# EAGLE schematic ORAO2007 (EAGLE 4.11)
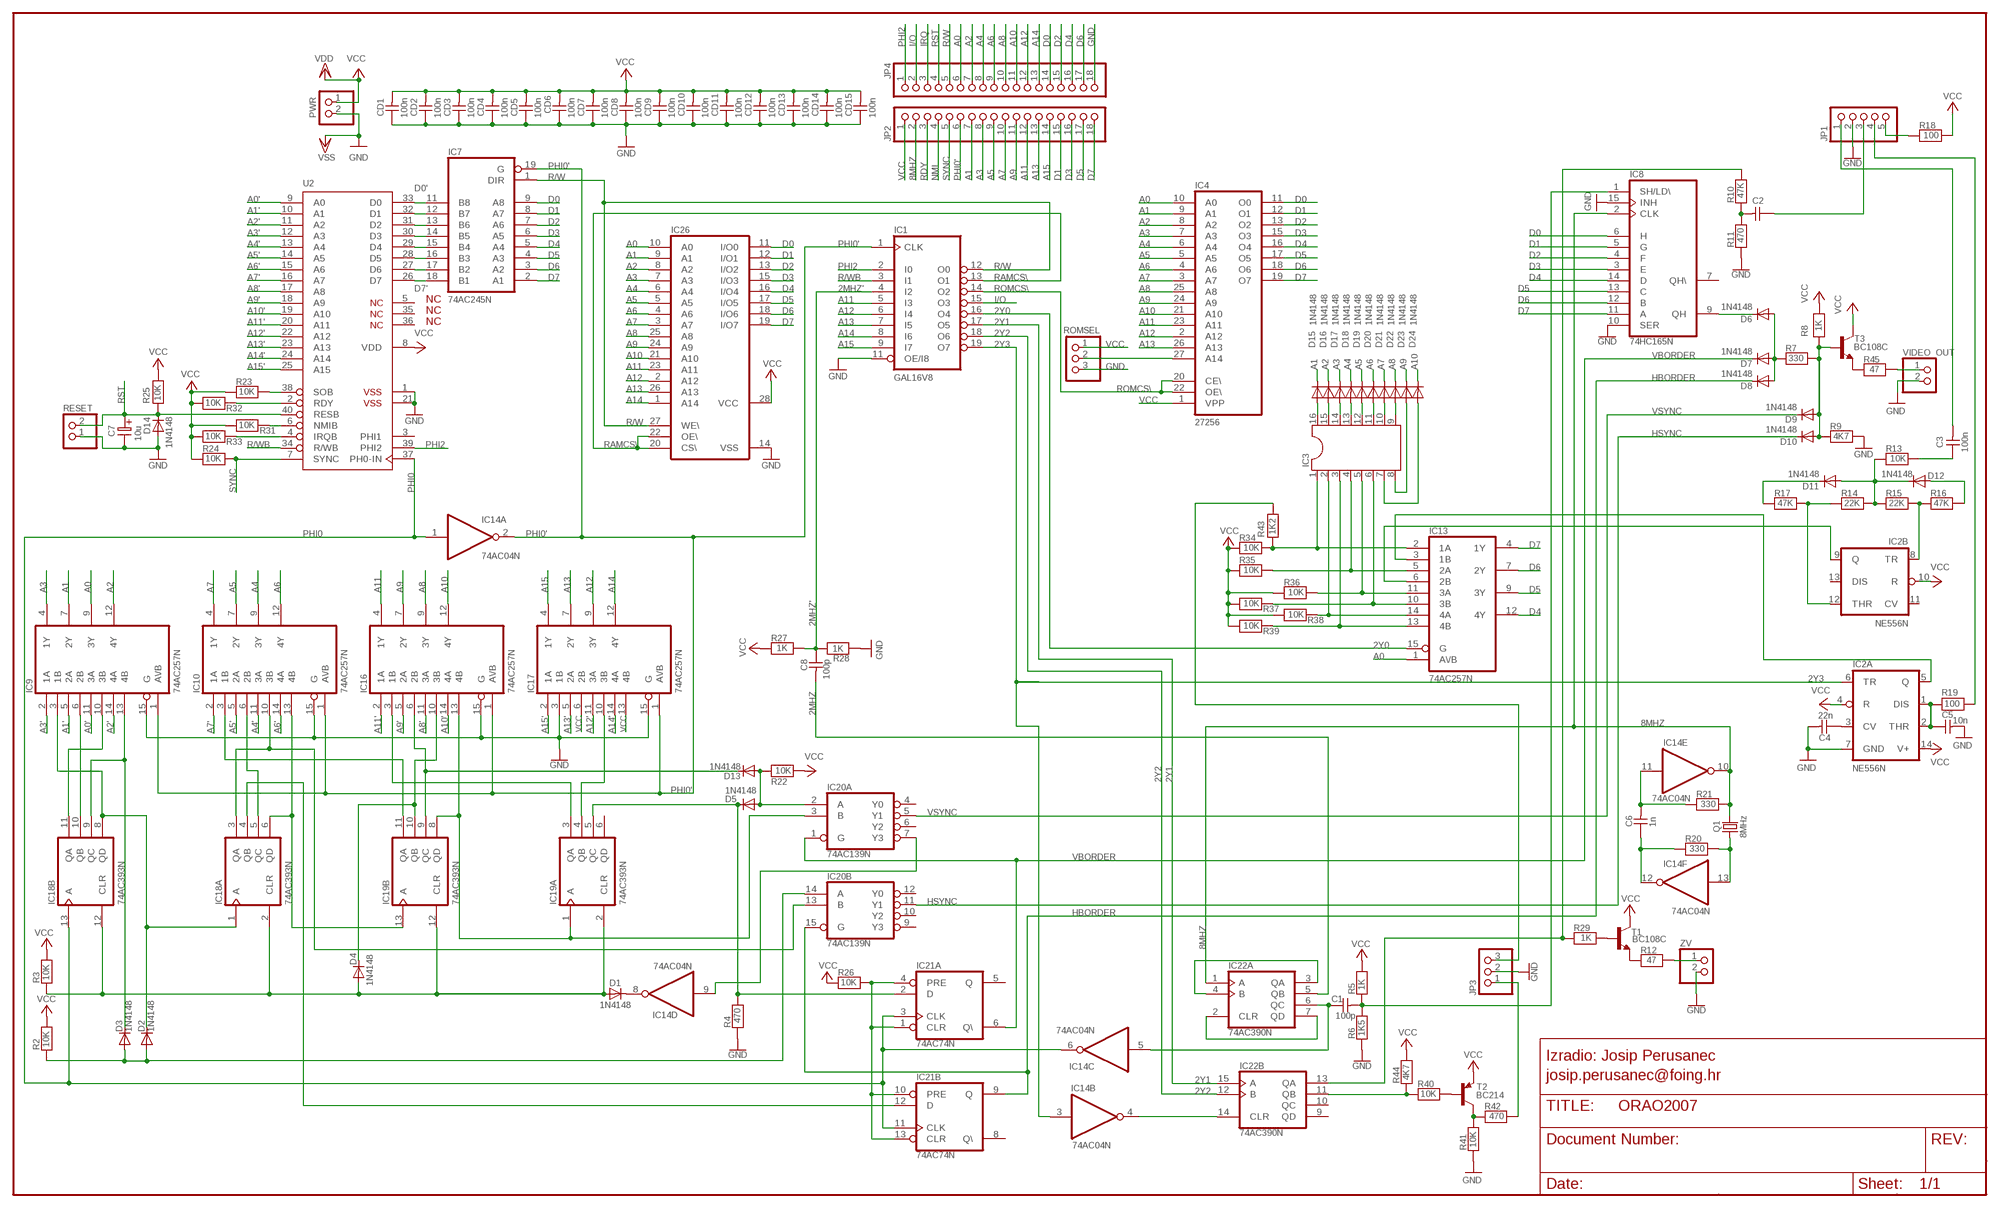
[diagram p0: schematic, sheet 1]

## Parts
C1  100p  CAPNP-5  [C-5]
C2  CAPNP-5  [C-5]
C3  100n  CAPNP-5  [C-5]
C4  22n  CAPNP-5  [C-5]
C5  10n  CAPNP-5  [C-5]
C6  1n  CAPNP-5  [C-5]
C7  10u  ELC-2,5L  [ES-2,5L]
C8  100p  CAPNP-5  [C-5]
CD1  100n  CAPNP-5  [C-5]
CD2  100n  CAPNP-5  [C-5]
CD3  100n  CAPNP-5  [C-5]
CD4  100n  CAPNP-5  [C-5]
CD5  100n  CAPNP-5  [C-5]
CD6  100n  CAPNP-5  [C-5]
CD7  100n  CAPNP-5  [C-5]
CD8  100n  CAPNP-5  [C-5]
CD9  100n  CAPNP-5  [C-5]
CD10  100n  CAPNP-5  [C-5]
CD11  100n  CAPNP-5  [C-5]
CD12  100n  CAPNP-5  [C-5]
CD13  100n  CAPNP-5  [C-5]
CD14  100n  CAPNP-5  [C-5]
CD15  100n  CAPNP-5  [C-5]
D1  1N4148  [DO35-10]
D2  1N4148  [DO35-10]
D3  1N4148  [DO35-10]
D4  1N4148  [DO35-10]
D5  1N4148  [DO35-10]
D6  1N4148  [DO35-10]
D7  1N4148  [DO35-10]
D8  1N4148  [DO35-10]
D9  1N4148  [DO35-10]
D10  1N4148  [DO35-10]
D11  1N4148  [DO35-10]
D12  1N4148  [DO35-10]
D13  1N4148  [DO35-10]
D14  1N4148  [DO35-10]
D15  1N4148  [DO35-10]
D16  1N4148  [DO35-10]
D17  1N4148  [DO35-10]
D18  1N4148  [DO35-10]
D19  1N4148  [DO35-10]
D20  1N4148  [DO35-10]
D21  1N4148  [DO35-10]
D22  1N4148  [DO35-10]
D23  1N4148  [DO35-10]
D24  1N4148  [DO35-10]
IC1  GAL16V8  16V8  [DIL20]
IC2  NE556N  [DIL14]
IC3  DIL16S  [SOCKED-16]
IC4  27256  [DIL28]
IC7  74AC245N  [DIL20]
IC8  74HC165N  [DIL16]
IC9  74AC257N  [DIL16]
IC10  74AC257N  [DIL16]
IC13  74AC257N  [DIL16]
IC14  74AC04N  [DIL14]
IC16  74AC257N  [DIL16]
IC17  74AC257N  [DIL16]
IC18  74AC393N  [DIL14]
IC19  74AC393N  [DIL14]
IC20  74AC139N  [DIL16]
IC21  74AC74N  [DIL14]
IC22  74AC390N  [DIL16]
IC26  62256P  [DIL28-6]
JP1  PINHD-1X5  [1X05]
JP2  PINHD-1X18  [1X18]
JP3  PINHD-1X3  [1X03]
JP4  PINHD-1X18  [1X18]
PWR  PINHD-1X2  [1X02]
Q1  8MHz  CRYTALHC49S  [HC49/S]
R2  10K  RESEU-7,5  [R-7,5]
R3  10K  RESEU-7,5  [R-7,5]
R4  470  RESEU-7,5  [R-7,5]
R5  1K  RESEU-7,5  [R-7,5]
R6  1K5  RESEU-7,5  [R-7,5]
R7  330  RESEU-7,5  [R-7,5]
R8  1K  RESEU-7,5  [R-7,5]
R9  4K7  RESEU-7,5  [R-7,5]
R10  47K  RESEU-7,5  [R-7,5]
R11  470  RESEU-7,5  [R-7,5]
R12  47  RESEU-7,5  [R-7,5]
R13  10K  RESEU-7,5  [R-7,5]
R14  22K  RESEU-7,5  [R-7,5]
R15  22K  RESEU-7,5  [R-7,5]
R16  47K  RESEU-7,5  [R-7,5]
R17  47K  RESEU-7,5  [R-7,5]
R18  100  RESEU-7,5  [R-7,5]
R19  100  RESEU-7,5  [R-7,5]
R20  330  RESEU-7,5  [R-7,5]
R21  330  RESEU-7,5  [R-7,5]
R22  10K  RESEU-7,5  [R-7,5]
R23  10K  RESEU-7,5  [R-7,5]
R24  10K  RESEU-7,5  [R-7,5]
R25  10K  RESEU-7,5  [R-7,5]
R26  10K  RESEU-7,5  [R-7,5]
R27  1K  RESEU-7,5  [R-7,5]
R28  1K  RESEU-7,5  [R-7,5]
R29  1K  RESEU-7,5  [R-7,5]
R31  10K  RESEU-7,5  [R-7,5]
R32  10K  RESEU-7,5  [R-7,5]
R33  10K  RESEU-7,5  [R-7,5]
R34  10K  RESEU-7,5  [R-7,5]
R35  10K  RESEU-7,5  [R-7,5]
R36  10K  RESEU-7,5  [R-7,5]
R37  10K  RESEU-7,5  [R-7,5]
R38  10K  RESEU-7,5  [R-7,5]
R39  10K  RESEU-7,5  [R-7,5]
R40  10K  RESEU-7,5  [R-7,5]
R41  10K  RESEU-7,5  [R-7,5]
R42  470  RESEU-7,5  [R-7,5]
R43  1K2  RESEU-7,5  [R-7,5]
R44  4K7  RESEU-7,5  [R-7,5]
R45  47  RESEU-7,5  [R-7,5]
RESET  PINHD-1X2  [1X02]
ROMSEL  PINHD-1X3  [1X03]
T1  BC108C  [TO18]
T2  BC214  [TO92]
T3  BC108C  [TO18]
U2  G65SC02P  [DIP-40]
VIDEO_OUT  PINHD-1X2  [1X02]
ZV  PINHD-1X2  [1X02]

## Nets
1B9: D2.C IC9.3(1B) IC18.1(A:A) IC18.8(B:QD)
1B10: IC10.3(1B) IC19.11(B:QA)
1B16: IC16.3(1B) IC19.3(A:QA)
2B10: IC10.6(2B) IC18.5(A:QC)
2B16: D13.C IC16.6(2B) IC19.9(B:QC)
2MHZ: C8.2 IC22.5(A:QB)
2MHZ': C8.1 IC1.4(I2) R27.1 R28.2
2Y0: IC1.16(O4) IC13.15(G)
2Y1: IC1.17(O5) IC22.15(B:A)
2Y2: IC1.18(O6) IC22.12(B:B)
2Y3: IC1.19(O7) IC2.6(A:TR) IC14.3(B:I)
3B9: IC9.10(3B) IC18.11(B:QA)
3B10: IC10.10(3B) IC18.3(A:QA) IC20.13(B:B)
3B16: D4.C IC16.10(3B) IC19.10(B:QB)
3B17: IC17.10(3B) IC19.4(A:QB)
4B9: D3.C IC9.13(4B) IC18.9(B:QC)
4B10: IC10.13(4B) IC18.6(A:QD) IC19.13(B:A)
4B16: IC16.13(4B) IC19.1(A:A) IC19.8(B:QD) IC20.3(A:B)
8MHZ: IC8.2(CLK) IC14.10(E:O) IC22.1(A:A) JP2.2 Q1.2 R21.2
A0: IC4.10(A0) IC9.9(3Y) IC13.1(A\/B) IC26.10(A0) JP4.6
A0': IC9.11(3A) U2.9(A0)
A1: D15.C IC4.9(A1) IC9.7(2Y) IC26.9(A1) JP2.7
A1': IC9.5(2A) U2.10(A1)
A2: D16.C IC4.8(A2) IC9.12(4Y) IC26.8(A2) JP4.7
A2': IC9.14(4A) U2.11(A2)
A3: D17.C IC4.7(A3) IC9.4(1Y) IC26.7(A3) JP2.8
A3': IC9.2(1A) U2.12(A3)
A4: D18.C IC4.6(A4) IC10.9(3Y) IC26.6(A4) JP4.8
A4': IC10.11(3A) U2.13(A4)
A5: D19.C IC4.5(A5) IC10.7(2Y) IC26.5(A5) JP2.9
A5': IC10.5(2A) U2.14(A5)
A6: D20.C IC4.4(A6) IC10.12(4Y) IC26.4(A6) JP4.9
A6': IC10.14(4A) U2.15(A6)
A7: D21.C IC4.3(A7) IC10.4(1Y) IC26.3(A7) JP2.10
A7': IC10.2(1A) U2.16(A7)
A8: D22.C IC4.25(A8) IC16.9(3Y) IC26.25(A8) JP4.10
A8': IC16.11(3A) U2.17(A8)
A9: D23.C IC4.24(A9) IC16.7(2Y) IC26.24(A9) JP2.11
A9': IC16.5(2A) U2.18(A9)
A10: D24.C IC4.21(A10) IC16.12(4Y) IC26.21(A10) JP4.11
A10': IC16.14(4A) U2.19(A10)
A11: IC1.5(I3) IC4.23(A11) IC16.4(1Y) IC26.23(A11) JP2.12
A11': IC16.2(1A) U2.20(A11)
A12: IC1.6(I4) IC4.2(A12) IC17.9(3Y) IC26.2(A12) JP4.12
A12': IC17.11(3A) U2.22(A12)
A13: IC1.7(I5) IC4.26(A13) IC17.7(2Y) IC26.26(A13) JP2.13
A13': IC17.5(2A) U2.23(A13)
A14: IC1.8(I6) IC17.12(4Y) IC26.1(A14) JP4.13
A14': IC17.14(4A) U2.24(A14)
A15: IC1.9(I7) IC17.4(1Y) JP2.14
A15': IC17.2(1A) U2.25(A15)
D0: IC4.11(O0) IC7.9(A8) IC8.6(H) IC26.11(I/O0) JP4.14
D0': IC7.11(B8) U2.33(D0)
D1: IC4.12(O1) IC7.8(A7) IC8.5(G) IC26.12(I/O1) JP2.15
D1': IC7.12(B7) U2.32(D1)
D2: IC4.13(O2) IC7.7(A6) IC8.4(F) IC26.13(I/O2) JP4.15
D2': IC7.13(B6) U2.31(D2)
D3: IC4.15(O3) IC7.6(A5) IC8.3(E) IC26.15(I/O3) JP2.16
D3': IC7.14(B5) U2.30(D3)
D4: IC4.16(O4) IC7.5(A4) IC8.14(D) IC13.12(4Y) IC26.16(I/O4) JP4.16
D4': IC7.15(B4) U2.29(D4)
D5: IC4.17(O5) IC7.4(A3) IC8.13(C) IC13.9(3Y) IC26.17(I/O5) JP2.17
D5': IC7.16(B3) U2.28(D5)
D6: IC4.18(O6) IC7.3(A2) IC8.12(B) IC13.7(2Y) IC26.18(I/O6) JP4.17
D6': IC7.17(B2) U2.27(D6)
D7: IC4.19(O7) IC7.2(A1) IC8.11(A) IC13.4(1Y) IC26.19(I/O7) JP2.18
D7': IC7.18(B1) U2.26(D7)
GND [gnd]: C4.2 C5.2 C7.2 CD1.1 CD2.1 CD3.1 CD4.1 CD5.1 CD6.1 CD7.1 CD8.1 CD9.1 CD10.1 CD11.1 CD12.1 CD13.1 CD14.1 CD15.1 D14.A IC1.11(OE/I8) IC2.7(A:GND) IC8.10(SER) IC8.15(INH) IC9.15(G) IC10.15(G) IC16.15(G) IC17.3(1B) IC17.15(G) IC26.14(VSS) JP1.2 JP3.2 JP4.18 PWR.2 R4.1 R6.1 R9.2 R11.1 R28.1 R41.2 RESET.1 ROMSEL.3 U2.1(VSS$1) U2.21(VSS$2) VIDEO_OUT.2 ZV.2 ; supply symbol labelled VSS
HBORDER: D8.C IC20.15(B:G) IC21.9(B:Q)
HSYNC: D10.C IC20.11(B:Y1)
I/O: IC1.15(O3) JP4.2
IRQ: JP4.3 R33.2 U2.4(IRQB)
N$1: R45.1 T3.1(E)
N$2: D15.A IC3.16
N$3: IC4.27(A14) ROMSEL.2
N$4: R45.2 VIDEO_OUT.1
N$5: D1.C IC14.8(D:O)
N$7: IC14.9(D:I) IC20.7(A:Y3)
N$8: D2.A D3.A IC20.14(B:A) R2.2
N$9: D1.A D4.A IC18.2(A:CLR) IC18.12(B:CLR) IC19.2(A:CLR) IC19.12(B:CLR) R3.2
N$14: C2.1 JP1.3
N$15: D5.C IC19.5(A:QC) IC21.2(A:D) R4.2
N$17: IC18.4(A:QB) IC21.12(B:D)
N$18: D5.A D13.A IC20.2(A:A) R22.1
N$20: C1.1 IC14.5(C:I) IC22.6(A:QC)
N$21: C1.2 IC8.1(SH/LD\) R5.1 R6.2
N$22: IC21.1(A:CLR) IC21.4(A:PRE) IC21.10(B:PRE) IC21.13(B:CLR) R26.2
N$23: D6.C IC8.9(QH)
N$24: D6.A D7.A D8.A R7.1
N$26: D9.A D10.A R7.2 R8.1 R9.1 T3.2(B)
N$27: D11.A D12.C R13.2 R14.2 R15.1
N$28: C2.2 R10.2 R11.2
N$29: IC22.13(B:QA) R10.1 R29.2
N$30: R29.1 T1.2(B)
N$31: R12.1 T1.1(E)
N$32: R12.2 ZV.1
N$33: JP1.5 R18.2
N$34: C3.1 R13.1
N$37: D16.A IC3.15
N$38: C3.2 JP1.1
N$39: IC2.8(B:TR) R15.2 R16.1
N$40: D12.A R16.2
N$41: IC2.12(B:THR) R14.1 R17.2
N$42: D11.C R17.1
N$43: IC2.9(B:Q) IC13.6(2B)
N$44: JP3.1 R42.1
N$46: IC2.5(A:Q) IC13.3(1B)
N$47: C4.1 IC2.3(A:CV)
N$48: C5.1 IC2.1(A:DIS) IC2.2(A:THR) R19.1
N$49: JP1.4 R19.2
N$50: IC14.13(F:I) Q1.1 R20.2
N$51: IC14.4(B:O) IC22.14(B:CLR)
N$52: C6.2 IC14.11(E:I) R21.1
N$53: C6.1 IC14.12(F:O) R20.1
N$54: R23.2 U2.38(SOB)
N$55: D17.A IC3.14
N$56: D18.A IC3.13
N$62: IC9.6(2B) IC18.10(B:QB)
N$64: D19.A IC3.12
N$70: IC3.5 IC13.11(3A) R36.2
N$71: IC3.2 IC13.14(4A) R38.2
N$72: IC3.6 IC13.10(3B) R37.2
N$73: IC3.4 IC13.5(2A) R35.2
N$74: IC3.1 IC13.2(1A) R34.2 R43.1
N$75: IC3.3 IC13.13(4B) R39.2
N$76: IC22.2(A:CLR) IC22.7(A:QD)
N$77: IC22.3(A:QA) IC22.4(A:B)
N$78: IC22.11(B:QB) R40.1 R44.1
N$79: R40.2 T2.2(B)
N$80: R41.1 R42.2 T2.3(C)
N$81: JP3.3 R43.2
N$82: D20.A IC3.11
N$83: D21.A IC3.10
N$84: D22.A IC3.9
N$85: D23.A IC3.8
N$86: D24.A IC3.7
NMI: JP2.4 R31.2 U2.6(NMIB)
PHI0: IC14.1(A:I) IC14.6(C:O) IC18.13(B:A) IC21.3(A:CLK) IC21.11(B:CLK) U2.37(PH0-IN)
PHI0': IC1.1(CLK) IC7.19(G) IC9.1(A\/B) IC10.1(A\/B) IC14.2(A:O) IC16.1(A\/B) IC17.1(A\/B) JP2.6
PHI2: IC1.2(I0) JP4.1 U2.39(PHI2)
R/W: IC1.12(O0) IC7.1(DIR) IC26.27(WE\) JP4.5
R/WB: IC1.3(I1) U2.34(R/WB)
RAMCS\: IC1.13(O1) IC26.20(CS\) IC26.22(OE\)
RDY: JP2.3 R32.2 U2.2(RDY)
ROMCS\: IC1.14(O2) IC4.20(CE\) IC4.22(OE\)
RST: C7.1 D14.C JP4.4 R25.1 RESET.2 U2.40(RESB)
SYNC: JP2.5 R24.2 U2.7(SYNC)
VBORDER: D7.C IC20.1(A:G) IC21.6(A:Q\)
VCC [vcc]: CD1.2 CD2.2 CD3.2 CD4.2 CD5.2 CD6.2 CD7.2 CD8.2 CD9.2 CD10.2 CD11.2 CD12.2 CD13.2 CD14.2 CD15.2 IC2.4(A:R) IC2.10(B:R) IC2.14(A:V+) IC4.1(VPP) IC17.6(2B) IC17.13(4B) IC26.28(VCC) JP2.1 PWR.1 R2.1 R3.1 R5.2 R8.2 R18.1 R22.2 R23.1 R24.1 R25.2 R26.1 R27.2 R31.1 R32.1 R33.1 R34.1 R35.1 R36.1 R37.1 R38.1 R39.1 R44.2 ROMSEL.1 T1.3(C) T2.1(E) T3.3(C) U2.8(VDD) ; supply symbol labelled VDD
VSYNC: D9.C IC20.5(A:Y1)
Unconnected: IC2.11(B:CV) IC2.13(B:DIS) IC8.7(QH\) IC19.6(A:QD) IC20.4(A:Y0) IC20.6(A:Y2) IC20.9(B:Y3) IC20.10(B:Y2) IC20.12(B:Y0) IC21.5(A:Q) IC21.8(B:Q\) IC22.9(B:QD) IC22.10(B:QC) U2.3(PHI1) U2.5(NC$1) U2.35(NC$2) U2.36(NC$3)

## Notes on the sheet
- Izradio: Josip Perusanec
- josip.perusanec@foing.hr

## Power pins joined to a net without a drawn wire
GND: IC1.10(GND) IC4.14(GND) IC7.10(GND) IC8.8(GND) IC9.8(GND) IC10.8(GND) IC13.8(GND) IC14.7(P:GND) IC16.8(GND) IC17.8(GND) IC18.7(P:GND) IC19.7(P:GND) IC20.8(P:GND) IC21.7(P:GND) IC22.8(P:GND)
VCC: IC1.20(VCC) IC4.28(VCC) IC7.20(VCC) IC8.16(VCC) IC9.16(VCC) IC10.16(VCC) IC13.16(VCC) IC14.14(P:VCC) IC16.16(VCC) IC17.16(VCC) IC18.14(P:VCC) IC19.14(P:VCC) IC20.16(P:VCC) IC21.14(P:VCC) IC22.16(P:VCC)

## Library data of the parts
C1-C6 C8 CD1-CD15 = discrete:CAPNP-5
C7 = discrete:ELC-2,5L
D1-D24 = diode:1N4148: DIODE
IC1 = pal:16V8: PAL
IC2 = linear:*556: Dual TIMER
IC3 = ic-package:DIL16: Dual In Line
IC4 = memory:27256: MEMORY
IC7 = 74xx-eu:74*245: Octal BUS TRANSCEIVER, 3-state
IC8 = 74xx-eu:74*165: 8-bit parallel load SHIFT REGISTER
IC9 IC10 IC13 IC16 IC17 = 74xx-eu:74*257: Quadruple 2-to 1 line data SELECTOR/MULTIPLEXER
IC14 = 74xx-eu:74*04: Hex INVERTER
IC18 IC19 = 74xx-eu:74*393: Dual 4-bit decade and binary COUNTER
IC20 = 74xx-eu:74*139: Dual 2-line to 4-line DECODER/DEMULTIPLEXER
IC21 = 74xx-eu:74*74: Dual D type positive edge triggered FLIP FLOP, preset and clear
IC22 = 74xx-eu:74*390: Dual 4-bit decade and binary COUNTER
IC26 = memory-hitachi:62256P: MEMORY
JP1 = pinhead:PINHD-1X5: PIN HEADER
JP2 JP4 = pinhead:PINHD-1X18: PIN HEADER
JP3 ROMSEL = pinhead:PINHD-1X3: PIN HEADER
PWR RESET VIDEO_OUT ZV = pinhead:PINHD-1X2: PIN HEADER
Q1 = crystal:CRYTAL: CRYSTAL
R2-R29 R31-R45 = discrete:RESEU-7,5
T1 T3 = transistor-npn:BC108C: NPN Transistor
T2 = transistor-pnp:BC214: PNP Transistor
U2 = 65xxx:G65SC02P: California Micro Devices Version

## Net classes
0 default: width 0.406 mm, drill 0.203 mm
1 gnd: width 0.813 mm, drill 0.203 mm
2 vcc: width 0.813 mm, drill 0.203 mm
